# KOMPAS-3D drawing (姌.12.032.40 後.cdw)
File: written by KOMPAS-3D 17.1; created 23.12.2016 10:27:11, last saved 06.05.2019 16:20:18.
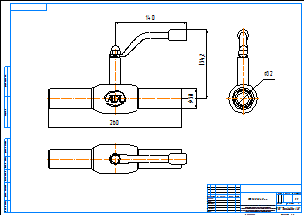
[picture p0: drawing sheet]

Sheet 1: A2, landscape

Title block, sheet 1: name: КШ.12.032.40 сс; material: Внимание! Данный продукт является объектом авторского права ООО «Торговый Дом АДЛ». / Запрещается изменение, копирование, распространение / (в том числе путем копирования на другие сайты и ресурсы в Интернете) / или любое иное использование информации и объектов без предварительного / согласия правообладателя (ООО «Торговый Дом АДЛ»).; sheets: 1; organisation: ООО "Торговый дом АДЛ"; sheet format: A2; stored path: C:\Users\tra\Desktop\2д чертежи\Шаровые краны БИВАЛ\КШ_Бивал_серия_11_12\KOMPAS_2D\КШ.12.032.40 сс.cdw

Views: Вид 1, Проекционный вид 2, Проекционный вид 3
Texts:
  Klimkovich
  ADL
Dimensions and other numbers on the sheet: 260; 38; 140; 134,2; 32; 1:1; 1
